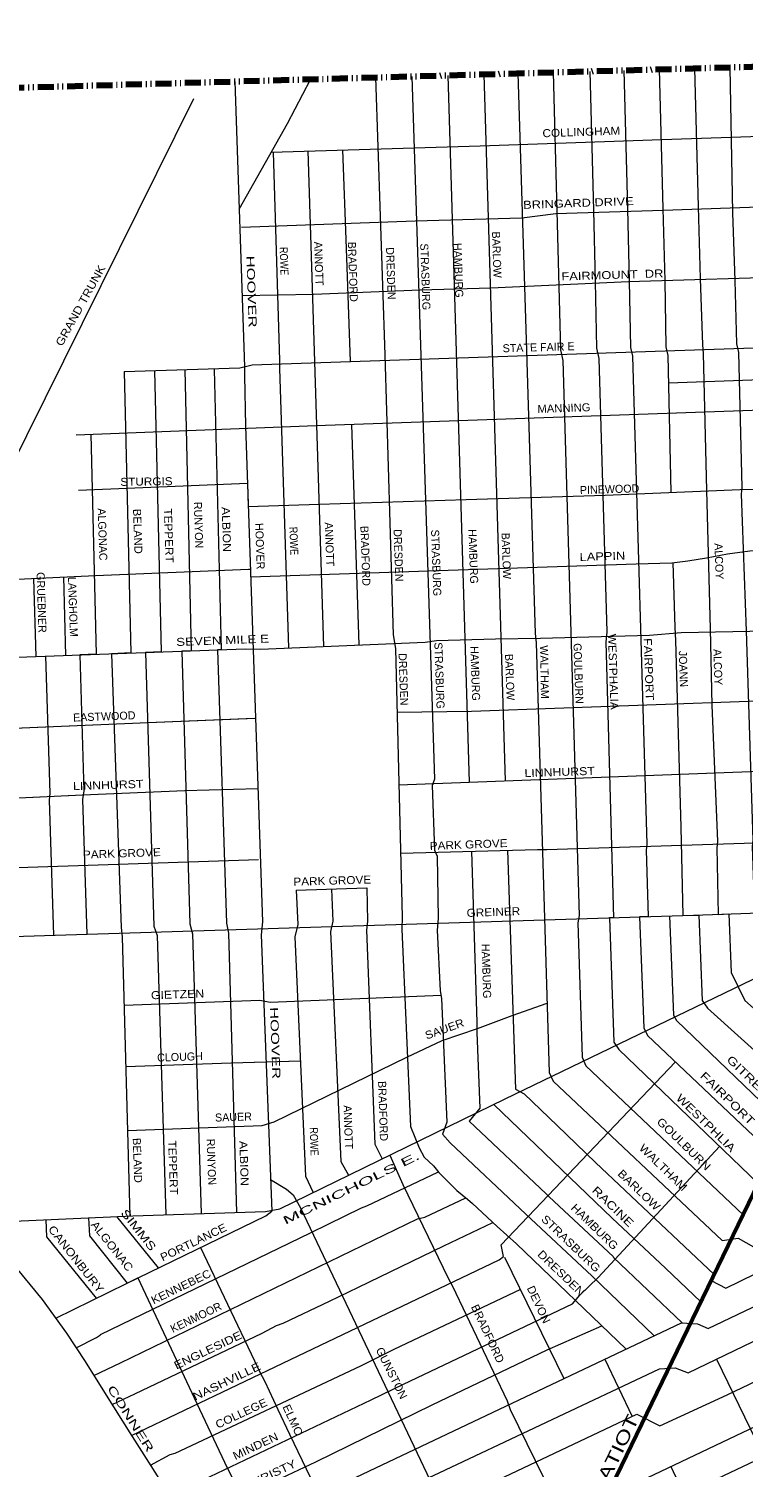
# Model space of a CAD drawing. Extents: x 34705 to 138605, y 34275 to 143551.
# Drawn here: x 109243 to 115941, y 129823 to 143301 of the extents above; entities that cross this region are included whole.
import ezdxf
from ezdxf.enums import TextEntityAlignment as Align

# ---------------------------------------------------------------- set-up
doc = ezdxf.new("R2010")
doc.units = 0
doc.header["$LTSCALE"] = 30
doc.linetypes.add('DASH_DOUBLE_DOT', pattern=[9.2, 5, -1.2, 0.3, -1.2, 0.3, -1.2])
for name, color, linetype, lineweight in [('1', 7, 'Continuous', 13), ('11', 7, 'Continuous', 13), ('50', 7, 'Continuous', 13), ('59', 7, 'DASH_DOUBLE_DOT', 106)]:
    doc.layers.add(name, color=color, linetype=linetype, lineweight=lineweight)

msp = doc.modelspace()

# ---------------------------------------------------------------- linework, layer by layer
at = {"layer": '1'}
for p, q in [((113508.93, 142872.51), (113710.64, 136254.23)), ((113509.94, 142872.58), (113509.94, 142872.54)), ((114161.12, 142891.16), (114161.12, 142891.12)), ((114502.69, 142900.9), (114502.69, 142900.86)), ((114822.56, 142910.02), (114822.56, 142909.98)), ((115153.9, 142919.48), (115153.9, 142919.43)), ((115485.55, 142928.94), (115485.55, 142928.9)), ((115817.8, 142938.42), (115817.8, 142938.37)), ((111175.68, 142805.99), (111175.68, 142805.96)), ((112495.74, 142843.65), (112495.74, 142843.61)), ((112834.49, 142853.31), (112834.49, 142853.28)), ((113171.43, 142862.89), (113372.74, 136241.47)), ((113172.45, 142862.95), (113172.45, 142862.92)), ((111857.92, 142156.04), (112007.48, 137513.1)), ((112269.95, 139593.92), (112338.17, 137527.1)), ((109568.24, 138164.74), (109586.37, 137429.58)), ((108770.55, 135431.09), (111396.79, 135518.47)), ((111748.91, 135228.75), (112413.12, 135252.27)), ((110064.37, 132170.88), (110456.9, 131689.55)), ((113704.21, 131790.96), (114260.75, 130652.87)), ((114644.26, 130834.69), (114898.72, 130299.1))]:
    msp.add_line(p, q, dxfattribs=at)
at = {"layer": '1', "lineweight": 53}
msp.add_lwpolyline([(101368.9, 103017.54), (102548.84, 105055.11), (103212.24, 106184.42), (103282.07, 106324.13), (104294.63, 108304.78), (105138.43, 110039.49), (106145.17, 112117.65), (109289.05, 118526.78), (110743.87, 121478.11), (113275.26, 126686.61), (116465.7, 133274.74), (120395.18, 141348.71), (121157.51, 142914.61), (121243.66, 143093.14)], dxfattribs=at)
at = {"layer": '1'}
for points in [[(113828.8, 142881.64), (113908.05, 140286.22), (113913.86, 140181.52), (113989.46, 137633.88), (114001.09, 137546.63), (114123.19, 133520.13), (114158.08, 133438.7), (115742.57, 131946.76), (115893.76, 131970.03), (116108.9, 131847.88), (116858.99, 130289.04), (117178.8, 129637.59), (117446.27, 129073.38), (119143.14, 125441.86)], [(114160.1, 142891.09), (114227.86, 140292.04), (114251.12, 140193.16), (114402.3, 134993.17), (114390.67, 134923.37), (114431.37, 133665.55), (114466.26, 133584.11), (115939.94, 132189.08)], [(114501.67, 142900.83), (114536.03, 141600.76), (114553.48, 140931.86), (114565.11, 140309.49), (114588.37, 140210.61), (114663.96, 137651.33), (114652.33, 137552.45), (114723.97, 134971.46), (114686.74, 134970.29), (114727.92, 133805.14), (114774.44, 133735.34), (116081.54, 132481.47)], [(114821.54, 142909.96), (114855.84, 141612.4), (114873.29, 140937.68), (114884.91, 140315.3), (114902.36, 140233.87), (115036.1, 135662.07), (115030.28, 135603.9), (115049.97, 134981.69), (114968.46, 134979.13), (115009.93, 133938.92), (115044.81, 133869.13), (116216.23, 132759.6)], [(115152.88, 142919.41), (115187.28, 141618.21), (115204.72, 140943.49), (115216.35, 140321.12), (115233.79, 140239.69), (115263.82, 138957.89)], [(115484.53, 142928.87), (115518.71, 141635.66), (115536.16, 140960.94), (115560.86, 140338.57), (115565.23, 140257.14), (115595.75, 138974.59), (115630.64, 137677.5), (115648.08, 136962.06), (115698.97, 135685.34), (115693.15, 135627.17), (115705.64, 135003.24), (115805.19, 135006.79), (115828.34, 134458.04), (115956.26, 134196.3), (116624.58, 133601.19)], [(115816.79, 142938.34), (115839.97, 141577.5), (115863.23, 140943.49), (115879.22, 140350.2), (115896.67, 140268.77), (115927.19, 139003.68), (115921.37, 138939.69), (115967.89, 137660.05), (116030.4, 135696.97), (116024.59, 135638.8), (116048.25, 135015.44), (116090.14, 135016.94), (116101.63, 134609.27), (116229.55, 134340.27), (116752.47, 133863.98)], [(111174.67, 142805.93), (111265.29, 140134.99), (111265.29, 140053.56), (111274, 139576.6), (111433.91, 134932.1), (111422.28, 134809.95), (111521.13, 132221.75)], [(111215.25, 141610.02), (111667.8, 142413.56), (111885.51, 142826.21)], [(112494.73, 142843.59), (112582.31, 140245.5), (112657.9, 137622.25), (112681.15, 137494.29), (112745.12, 134975.72), (112739.3, 134865.2), (112820.71, 133014.09), (112902.11, 132816.33), (112948.63, 132729.08), (113035.85, 132647.65), (113088.18, 132583.67), (113256.81, 132414.99), (113355.66, 132333.55), (113402.17, 132292.84), (113634.76, 132077.63), (113815.02, 131914.76), (114844.73, 130929.74)], [(112833.48, 142853.25), (113047.48, 136268.45), (113024.22, 136210.28), (113047.48, 135605.36), (113070.74, 135547.2), (113082.37, 134965.54), (113070.74, 134855.03), (113099.81, 134285), (113111.44, 134215.2), (113163.77, 133054.81), (113123.07, 132944.29), (113192.85, 132862.86), (113902.24, 132193.96), (114524.41, 131612.3), (115106.13, 131053.67)], [(111516.33, 142145.66), (113475.27, 142205.22), (115178.76, 142263.38), (117123.52, 142328.81), (120459.75, 142439.08)], [(111534.93, 142146.22), (111593.81, 140193.16), (111593.81, 140117.54), (111678.73, 137499.18)], [(112184.48, 142165.97), (112217.64, 141242.72), (112256.82, 140184.63)], [(111236.9, 141443.34), (112864.8, 141501.5), (113864.81, 141530.58), (114184.57, 141571.29), (115190.39, 141600.37), (117795.04, 141693.42), (120472.37, 141782.12)], [(111242.61, 140803.28), (111911.31, 140815.23), (112911.32, 140855.94), (113574.11, 140873.39), (114864.81, 140931.55), (116524.44, 140984.34)], [(110137.72, 140089.46), (111220.91, 140124.6), (111337.19, 140153.68), (121014.6, 140479.37), (122508.88, 140520.08), (123811.29, 140549.16), (125129.68, 140592.9), (126993.76, 140604.85)], [(115239.77, 139984.51), (118542.13, 140101.34), (119722.36, 140142.05), (119861.9, 140130.42), (121857.23, 140192.59), (121858.88, 140149.88), (122507.6, 140173.15)], [(110137.72, 140089.46), (110200.08, 137452.34), (110019.29, 137445.63), (110108.17, 134879.75), (110119.8, 134792.5), (110189.07, 132176.58)], [(110422.64, 140098.7), (110485.56, 137462.93), (110337.93, 137457.45), (110416.34, 134891.38), (110445.42, 134804.13), (110526.96, 132188.04)], [(110706.71, 140107.92), (110766.76, 137473.36), (110678.51, 137470.08), (110753.6, 134914.65), (110776.85, 134821.58), (110858.23, 132199.27)], [(110980.37, 140108.82), (111047.37, 137483.76), (111013.5, 137482.51), (111096.66, 134920.47), (111114.11, 134827.4), (111189.35, 132210.5)], [(109686.02, 139496.49), (111936.03, 139583.73), (113273.24, 139630.25), (116559.57, 139746.57), (119668.17, 139854.91), (119647.62, 139812.68), (121869.07, 139886.69), (121871.78, 139816.97), (122515.58, 139843.88)], [(109825.72, 139501.91), (109876.1, 137440.32), (109720.05, 137434.53), (109759.29, 136160.84), (109747.66, 136079.4), (109788.71, 134816.58)], [(109709.28, 138978.88), (111292.32, 139044.49), (111299.87, 138825.3), (111965.1, 138845.11), (113343.01, 138891.64), (114645.33, 138932.35), (115912.78, 138984.7), (116547.94, 138990.51), (116611.9, 139007.96), (119106.08, 139083.56), (119256.22, 139008.47)], [(108664.22, 138121.05), (109867.71, 138179.21), (111303.76, 138237.37), (111320.11, 138237.28), (111322.59, 138165.33), (114938.93, 138286.81), (115270.33, 138298.44), (115421.49, 138315.89), (115595.91, 138344.97), (115793.58, 138379.86), (116002.89, 138408.94), (116590.1, 138426.39), (116700.56, 138420.57), (118925.85, 138493.26), (119005.88, 138494.1), (118966.04, 138412.22), (119013.06, 138411.84), (121049.49, 138481.62), (122550.35, 138528.72)], [(115280.98, 138299.67), (115299.2, 137692.05), (115305.02, 137569.9), (115357.35, 135819.12), (115374.11, 134991.87), (115523.89, 134996.77), (115555.05, 134196.3), (115607.38, 134123.6), (116492.07, 133329.2)], [(109288.33, 138151.21), (109309.25, 137419.29), (109399.34, 137422.63), (109439.48, 136137.57), (109433.67, 136073.59), (109474.66, 134806.72)], [(108625.74, 137393.94), (111271.54, 137492.08), (111414.62, 137487.99), (112959.8, 137553.42), (113066.08, 137569.78), (113617.93, 137586.13), (114039.99, 137590.22), (115061.93, 137618.85), (115360.34, 137643.38), (116165.63, 137659.74), (116983.18, 137680.18), (118549.98, 137736.32), (118730.11, 137736.32), (121134.31, 137827.39), (121297.82, 137839.66), (122532.33, 137884.64), (122945.2, 137909.17), (123954.88, 137929.62), (124504.68, 137941.88), (124766.3, 137941.88), (125506.31, 137964.32)], [(112696.33, 136896.73), (113392.42, 136908.45), (115991.26, 137001.51), (117311.03, 137036.4), (118264.52, 137059.67), (118306.97, 137058.02), (118368.75, 137184.96), (118431.67, 137190.51), (119251.43, 137178.88), (119966.55, 137196.33), (121287.87, 137260.22), (121944.89, 137289.3), (123090.31, 137324.2), (123133.4, 137325.21), (123143.51, 137304.54), (123200.78, 137306.75), (125156.23, 137342.86)], [(108730.42, 136730.91), (110361.9, 136800.85), (111368.15, 136842.06)], [(108733.99, 136731.06), (110361.9, 136800.85), (111356.09, 136841.56)], [(112713.6, 136216.58), (117328.47, 136390.84), (117902.59, 136412.65), (118033.31, 136365.98), (119289.2, 136354.35), (120638.13, 136406.7), (121952.16, 136459.04), (122603.36, 136476.49), (123504.58, 136505.57), (123541.07, 136507.45), (123605.95, 136372.77), (123741.17, 136434.23), (124485.75, 136447.41), (124609.64, 136374.51)], [(108745.62, 136076.79), (109745.62, 136123.31), (110704.92, 136164.02), (111390.97, 136181.47)], [(108750.61, 136077.02), (109745.62, 136123.31), (110704.92, 136164.02), (111390.9, 136181.47)], [(112729.87, 135576.03), (114013.07, 135611.52), (114100.28, 135611.52), (116632.25, 135692.94), (116725.27, 135762.73), (117606.08, 135806.36), (117763.06, 135812.17), (118751.43, 135806.36), (119286.32, 135806.36), (121312.59, 135889.06), (121963.79, 135918.14), (123804.83, 135959.99)], [(113392.4, 135594.35), (113442.88, 133988.36), (113442.88, 133895.29), (113470.49, 133188.59), (113370.19, 133066.44), (114094.12, 132385.9), (114120.28, 132356.82), (114722.1, 131798.43), (114725.01, 131786.8), (115367.46, 131175.7)], [(113730.48, 135603.7), (113806.29, 133364.54), (113887.69, 133322.37), (114195.87, 133025.72), (114556.38, 132676.73), (115668.88, 131629.34)], [(111748.91, 135228.75), (111765.79, 134907.93), (111738.57, 134793.57), (111836.56, 132549.91), (111909.98, 132396.92)], [(112080.64, 135240.5), (112093.87, 134940.82), (112070.61, 134841.94), (112169.46, 132688.36), (112240.5, 132558.1)], [(112413.12, 135252.27), (112419.49, 134940.82), (112407.87, 134853.57), (112487.81, 132851.23), (112555.76, 132711.83), (112628.32, 132747.22), (112750.93, 132473.15), (113175.4, 131594.85), (113216.1, 131519.24), (113727.8, 130446.09), (113756.87, 130364.66), (114380.05, 129090.06)], [(108790.49, 134785.25), (115475.27, 134995.04), (117335.18, 135061.27)], [(115250.94, 134988), (115287.57, 134059.61), (115316.65, 134007.27), (116343.66, 133022.73)], [(108890.69, 132119.83), (110218.62, 132177.59), (111463.66, 132219.8), (111598.19, 132244.87), (113708.42, 133273.94), (116745.85, 134738.39), (117107.22, 134743.67), (117260.22, 134791.17), (117560.93, 134785.89), (119249.54, 134800.95), (119957.59, 134818.33), (120035.78, 134827.02), (120789.59, 134833.38), (121930.43, 134865.05), (122072.88, 134859.77), (123502.56, 134875.6), (123708.58, 134772.56)], [(110136.79, 134150.94), (111408.41, 134198.27), (111507.25, 134180.82), (113110.09, 134245.19)], [(110167.85, 132977.88), (111431.67, 133024.92), (111542.13, 133059.82), (112786.32, 133664.67), (112786.32, 133664.67), (113117.72, 133821.7), (113449.11, 133932.2), (113774.69, 134054.33), (114103.49, 134169.74)], [(110151.97, 133577.41), (111140.97, 133612.32), (111790.83, 133629.74)], [(110152.6, 133577.43), (111140.97, 133612.32), (111792.13, 133629.77)], [(110204.59, 130120.22), (111696.02, 130830.65), (113651.72, 131765.86), (113692.15, 131796.19), (113671.94, 131907.4), (115306.82, 133620.96)], [(113602.82, 133222.45), (114710.99, 132157.82), (115211.83, 131689.48), (115544.61, 131372.73)], [(110564.65, 129549.38), (110680.19, 129611.61), (112452.48, 130454.59), (112756.55, 130602.33), (114340.98, 131352.97), (114410.48, 131435.53), (114579.89, 131600.66), (115718.92, 132829.32)], [(109687.69, 130940.19), (109876.57, 131036.86), (109915.67, 131062.93), (109915.67, 131067.27), (111883.44, 132018.89), (112048.5, 132101.45), (112361.26, 132253.54), (112413.39, 132270.92), (113078, 132588.12)], [(111509.73, 132520.15), (111657.77, 132426.62), (111721.73, 132374.27), (111791.51, 132252.12), (113733.61, 128168.91), (113939.82, 128058.9)], [(110964.64, 129085.26), (111152.58, 129179.26), (115363.95, 131175.91), (115511.65, 131167.22), (115611.55, 131123.76), (118086.47, 132304.59), (118081.56, 132432.35)], [(111177.7, 128855.06), (111382.8, 128957.65), (112056.1, 129283.54), (112946.6, 129705.04), (113037.82, 129744.14), (115155.45, 130745.72), (115303.14, 130754.42), (115424.77, 130706.62), (116379.33, 131166.13), (117117.79, 131522.44), (117182.95, 131544.17), (118846.65, 132335.01), (118837.96, 132447.98)], [(115641.55, 131572.91), (115776.62, 131501.8), (117018.97, 132105.8), (117084.13, 132131.87), (117409.91, 132288.3), (117409.91, 132409.5)], [(109853.18, 130681.84), (110102.45, 130802.21), (112886.87, 132149.25), (112956.37, 132166.63), (113340.03, 132347.23)], [(111388.95, 128630.48), (111591.31, 128731.69), (112199.45, 129022.83), (113089.94, 129448.66), (113168.13, 129479.08), (114942.6, 130319.89), (115159.79, 130211.26), (115789.65, 130502.39), (119505.83, 132275.26)], [(114657.99, 129541.89), (118932.44, 131571.33), (119006.28, 131601.74), (119653.52, 131910.26), (120250.8, 132205.74), (122306.69, 132245.12)], [(109403.05, 132142.11), (109410.41, 131980.2), (109875.48, 131407.62)], [(109496.2, 131218.98), (110159.81, 131545.17), (111466.37, 132176.88), (111521.13, 132221.75)], [(109803.64, 132159.54), (109811.62, 131991.83), (110163.92, 131547.16), (110265.83, 131596.43), (110817.56, 130421.36), (111079.22, 129868.79), (111237.62, 129546.01)], [(110024.36, 130408.93), (110237.11, 130511.08), (111431.68, 131080.31), (111566.33, 131149.84), (111627.15, 131171.56), (112061.54, 131380.13), (112335.2, 131510.49), (113134.47, 131897.22), (113593.11, 132115.26)], [(112840.5, 128350.56), (113029.13, 128444.9), (113463.52, 128653.48), (114330.11, 129066.28), (115342.23, 129548.61), (116835.44, 130253.62), (117564.12, 130602.33), (120368.08, 131927.64), (122067.69, 131958.71)], [(110853.35, 131882.09), (111358.32, 130818.35), (111404.84, 130719.47), (111457.17, 130626.4), (111579.28, 130364.66), (111686.85, 130131.99), (112471.83, 128503.36)], [(109137.12, 131674.83), (109369.7, 131394.19), (109596.48, 131080.09), (109770.92, 130812.53), (109968.62, 130498.44), (110189.57, 130143.63), (110387.27, 129835.35), (110573.34, 129538.7), (110701.26, 129381.66), (111026.89, 129015.21), (111404.84, 128613.87), (113227.73, 126708.96), (113338.21, 126685.69), (114018.53, 125952.8), (115411.14, 123991.18), (115527.43, 123880.66), (115544.77, 123865.42)], [(110383.39, 129841.53), (110567.25, 129941.85), (110615.03, 129954.88), (112356.92, 130771.8), (112669.68, 130928.23), (113856.85, 131491.44)], [(110759.06, 129316.61), (111136.29, 129498.63), (111935.56, 129872.32), (113025.87, 130406.79), (114102.06, 130922.79), (114616.19, 131148.36)], [(115691.04, 130834.8), (116428.71, 129317.68), (116463.59, 129242.06), (116719.44, 128701.12), (116806.66, 128549.89), (117040.69, 128027.86), (117075.58, 127946.42), (118387.98, 125140.52)], [(115262.39, 129828.85), (115951.9, 128355.04), (116027.49, 128238.71), (117171.66, 125760.32)]]:
    msp.add_lwpolyline(points, dxfattribs=at)
at = {"layer": '50'}
msp.add_lwpolyline([(102381.37, 126834.33), (103625.89, 129138.56), (106032.14, 133515.49), (107949.49, 136936.41), (108177.8, 137385.22), (110790.54, 142647.36)], dxfattribs=at)
at = {"layer": '59'}
msp.add_lwpolyline([(131989.06, 109708.72), (126856.28, 120352.83), (127983.73, 120601.28), (129321.71, 120998.46), (130612.42, 121494.12), (133722.19, 123216.65), (134563.84, 124776.42), (136438.38, 130047.1), (136736.54, 131235.05), (136773.12, 131974.15), (125584.57, 138103.26), (128512.62, 143301.1), (34921.35, 140631.52)], dxfattribs=at)

# ---------------------------------------------------------------- texts
at = {"layer": '11'}
for s, height, rotation, width, p in [('COLLINGHAM', 75, 2.017, 1.1, (114424.69, 142297.07)), ('BRINGARD DRIVE', 75, 2.018, 1.2, (114397.08, 141631.46)), ('HOOVER', 75, 272.001, 1.55, (111294.15, 140836.84)), ('ROWE', 75, 271.998, 0.85, (111599.17, 141122.76)), ('GRAND TRUNK', 75, 61.095, 1.15, (109759.55, 140689.25)), ('FAIRMOUNT  DR', 75, 1.777, 1.2, (114715.82, 140957.63)), ('MANNING', 75, 1.923, 1.05, (114261.47, 139709.65)), ('STURGIS', 75, 0.903, 1.1, (110346.54, 139021.49)), ('BELAND', 75, 271.864, 1.05, (110227.26, 138591.05)), ('TEPPERT', 75, 271.866, 1.1, (110517.82, 138551.41)), ('ALBION', 75, 271.867, 1.15, (111058.68, 138608.68)), ('ROWE', 75, 271.998, 0.85, (111691.01, 138500.68)), ('LAPPIN', 75, 1.771, 1.2, (114622.06, 138321.4)), ('SEVEN MILE E', 75, 2.124, 1.25, (111061.25, 137533.7)), ('WESTPHALIA', 75, 272.001, 1.1, (114685.18, 137275)), ('FAIRPORT', 75, 271.998, 1.15, (115018.79, 137298.74)), ('LINNHURST', 75, 1.933, 1.15, (114221.24, 136299.93)), ('LINNHURST', 75, 1.933, 1.15, (109988.98, 136177.99)), ('PARK GROVE', 75, 1.932, 1.1, (110116.83, 135537.15)), ('PARK GROVE', 75, 2.201, 1.1, (113368.2, 135620.52)), ('PARK GROVE', 75, 1.655, 1.1, (112089.19, 135281.89)), ('GREINER', 75, 2.044, 1.1, (113600.02, 134987.75)), ('GIETZEN', 75, 1.985, 1.15, (110639.13, 134216.02)), ('HOOVER', 75, 271.983, 1.55, (111516.35, 133796.04)), ('SAUER', 75, 19.71, 1.1, (113153.07, 133893.62)), ('GITRE', 75, 315.838, 1.35, (115927.69, 133490.42)), ('FAIRPORT', 75, 315.835, 1.3, (115767, 133252.53)), ('WESTPHLIA', 75, 315.833, 1.25, (115564.93, 133022.09)), ('GOULBURN', 75, 315.835, 1.15, (115358.13, 132824.36)), ('BELAND', 75, 271.984, 1.05, (110224.99, 132696.59)), ('ROWE', 75, 271.82, 0.85, (111881.3, 132873.33)), ('TEPPERT', 75, 271.986, 1.1, (110558.42, 132628.66)), ('ALBION', 75, 271.984, 1.15, (111223.89, 132668.54)), ('WALTHAM', 75, 315.833, 1.15, (115164.9, 132604.24)), ('MCNICHOLS E.', 75, 26.097, 1.95, (112282.37, 132405.07)), ('BARLOW', 75, 316.374, 1.15, (114938.3, 132392.96)), ('RACINE', 75, 315.871, 1.3, (114693.62, 132237.94)), ('SIMMS ', 75, 308.167, 1.4, (110254.21, 132007.17)), ('HAMBURG', 75, 315.872, 1.1, (114521.95, 132048.77)), ('ALGONAC', 75, 308.164, 1.15, (109994.38, 131871.49)), ('PORTLANCE', 75, 25.803, 1.1, (110802.22, 131896.04)), ('STRASBURG', 75, 316.184, 1.15, (114299.82, 131891.25)), ('CANONBURY ', 75, 308.165, 1.2, (109667.42, 131736.26)), ('DRESDEN', 75, 316.183, 1.15, (114209.17, 131614.82)), ('KENNEBEC', 75, 25.809, 1.1, (110686.4, 131480.26)), ('DEVON', 75, 294.938, 1.05, (113989.67, 131331.55)), ('BRADFORD', 75, 294.937, 1.05, (113511.94, 131058.51)), ('ENGLESIDE', 75, 25.478, 1.2, (110937.72, 130885.13)), ('GUNSTON', 75, 296.566, 1.05, (112611.58, 130687.96)), ('NASHVILLE', 75, 25.47, 1.25, (111114.49, 130593.84)), ('CONNER', 75, 302.238, 1.65, (110166.34, 130257.68)), ('COLLEGE', 75, 25.126, 1.1, (111250.82, 130293.19)), ('ELMO', 75, 294.812, 1.1, (111684.99, 130247.76)), ('GRATIOT', 120, 64.201, 1.4, (114750.53, 129828.57)), ('MINDEN', 75, 25.438, 1.15, (111384.26, 129986.69)), ('CHRISTY', 75, 25.058, 1.2, (111518.86, 129717.61))]:
    msp.add_text(s, height=height, rotation=rotation, dxfattribs=dict(at, width=width)).set_placement(p, align=Align.CENTER)
for s, rotation, p in [('BARLOW', 272.001, (113593.21, 141182.96)), ('ANNOTT', 271.999, (111924.81, 141099.81)), ('BRADFORD', 272.001, (112244.21, 141022.73)), ('STRASBURG', 271.999, (112923.68, 140976.64)), ('HAMBURG', 272, (113233.81, 141036.66)), ('DRESDEN', 272, (112600.34, 141007.5)), ('STATE FAIR E     ', 1.717, (114093.21, 140281.43)), ('PINEWOOD', 1.801, (114689.32, 138949.69)), ('RUNYON', 271.866, (110797.23, 138649.78)), ('ALGONAC', 271.865, (109896.9, 138562.04)), ('HOOVER', 272.001, (111373.12, 138451.59)), ('ANNOTT', 271.999, (112025.02, 138469.81)), ('BRADFORD', 272.001, (112361.65, 138360.63)), ('DRESDEN', 272, (112671.39, 138365.69)), ('STRASBURG', 271.999, (113025.37, 138295.22)), ('HAMBURG', 272, (113373.16, 138355.21)), ('BARLOW', 272.001, (113682.68, 138360.38)), ('ALCOY', 272.002, (115677.33, 138310.06)), ('GRUEBNER', 271.864, (109325.08, 137924.4)), ('LANGHOLM', 271.865, (109620.02, 137882.99)), ('STRASBURG', 271.999, (113055.8, 137238.99)), ('HAMBURG', 272, (113391.53, 137258.99)), ('WALTHAM', 270.999, (114040.56, 137272.79)), ('GOULBURN', 272, (114359.35, 137258.49)), ('ALCOY', 272.002, (115666.28, 137318.71)), ('DRESDEN', 272, (112718.06, 137204.22)), ('BARLOW', 272.001, (113715.4, 137224.93)), ('JOANN', 272.001, (115342.75, 137301.58)), ('EASTWOOD', 2.2, (109951.88, 136820.65)), ('HAMBURG', 271.819, (113495.51, 134470.15)), ('CLOUGH', 1.982, (110661.98, 133630.6)), ('BRADFORD', 271.82, (112526.92, 133159.03)), ('ANNOTT', 271.82, (112201.08, 133007.76)), ('SAUER', 1.984, (111163.18, 133066.95)), ('RUNYON', 271.984, (110917.91, 132682.41)), ('KENMOOR', 25.817, (110826.41, 131192.72))]:
    msp.add_text(s, height=75, rotation=rotation, dxfattribs=at).set_placement(p, align=Align.CENTER)

doc.saveas('drawing.dxf')
